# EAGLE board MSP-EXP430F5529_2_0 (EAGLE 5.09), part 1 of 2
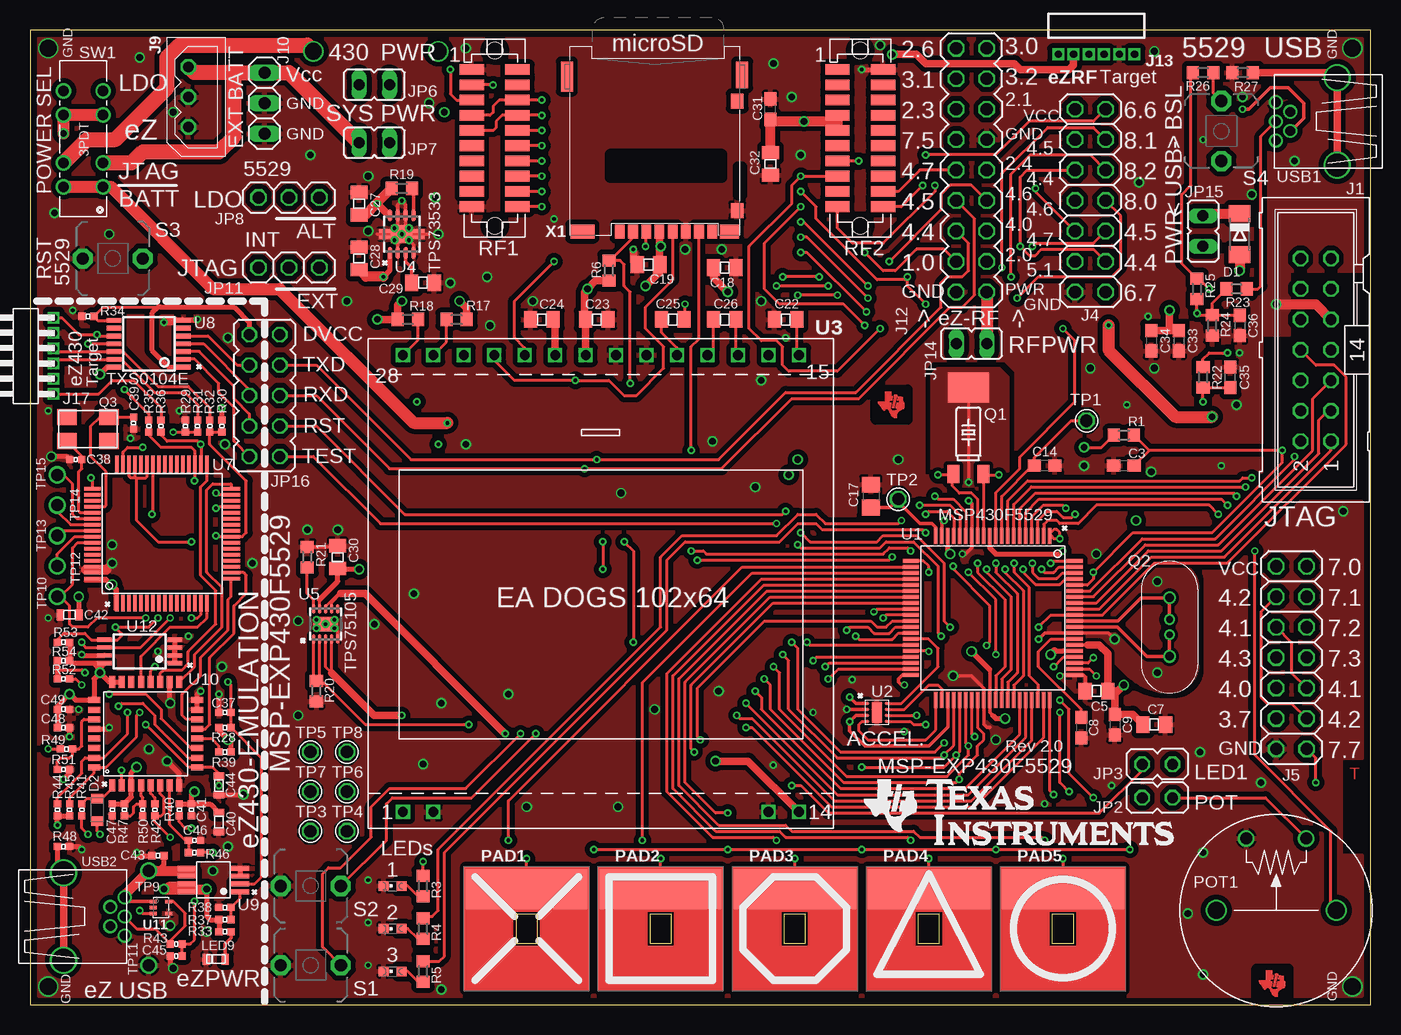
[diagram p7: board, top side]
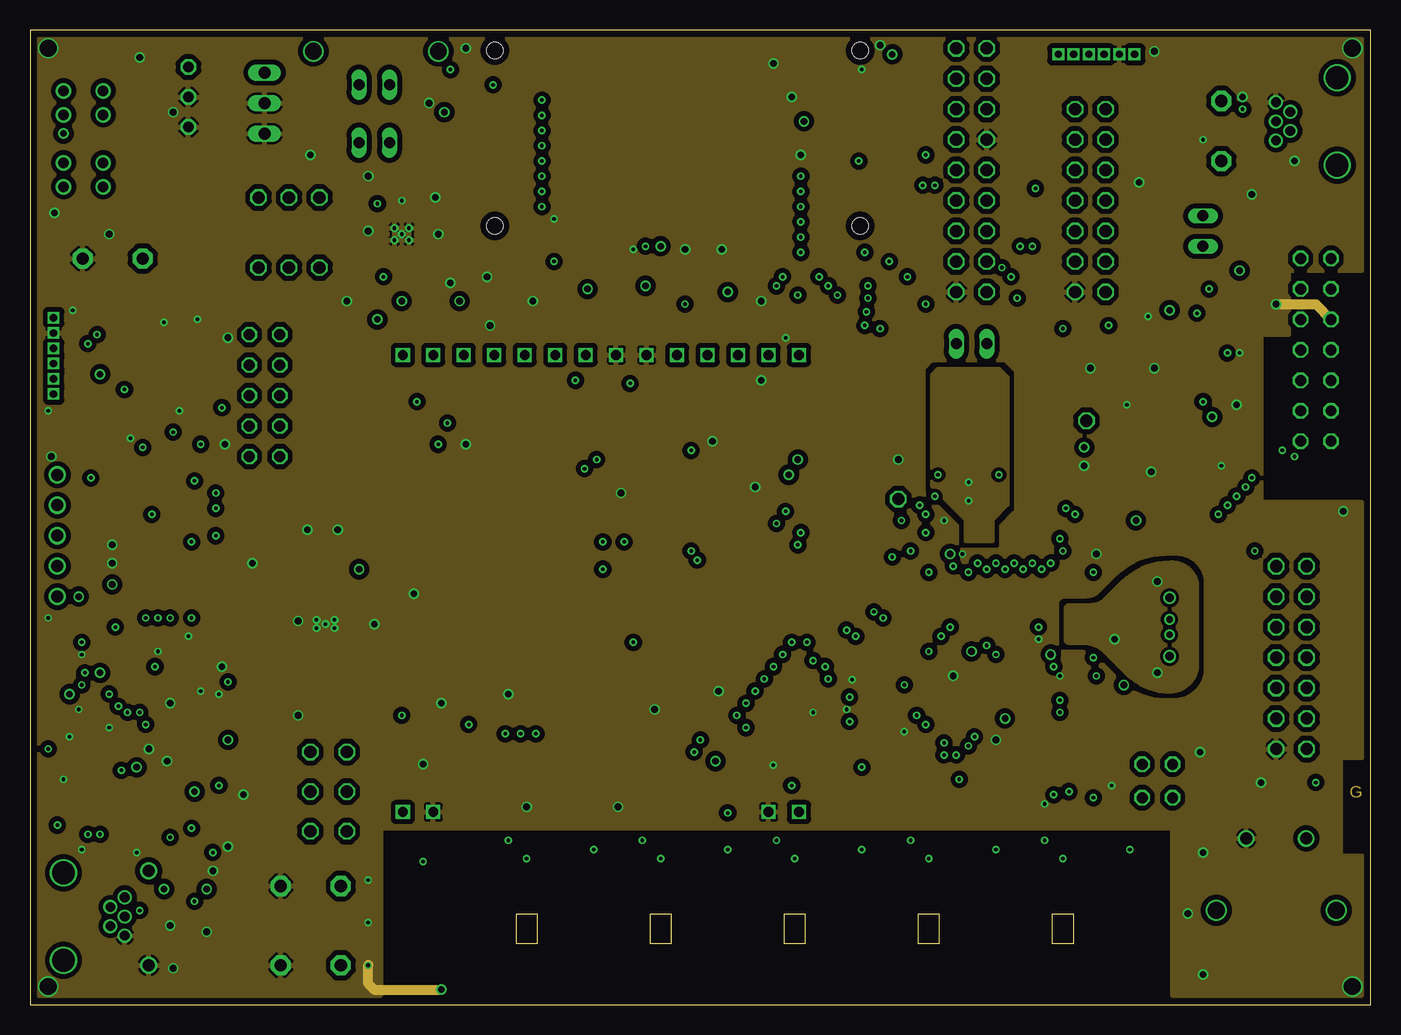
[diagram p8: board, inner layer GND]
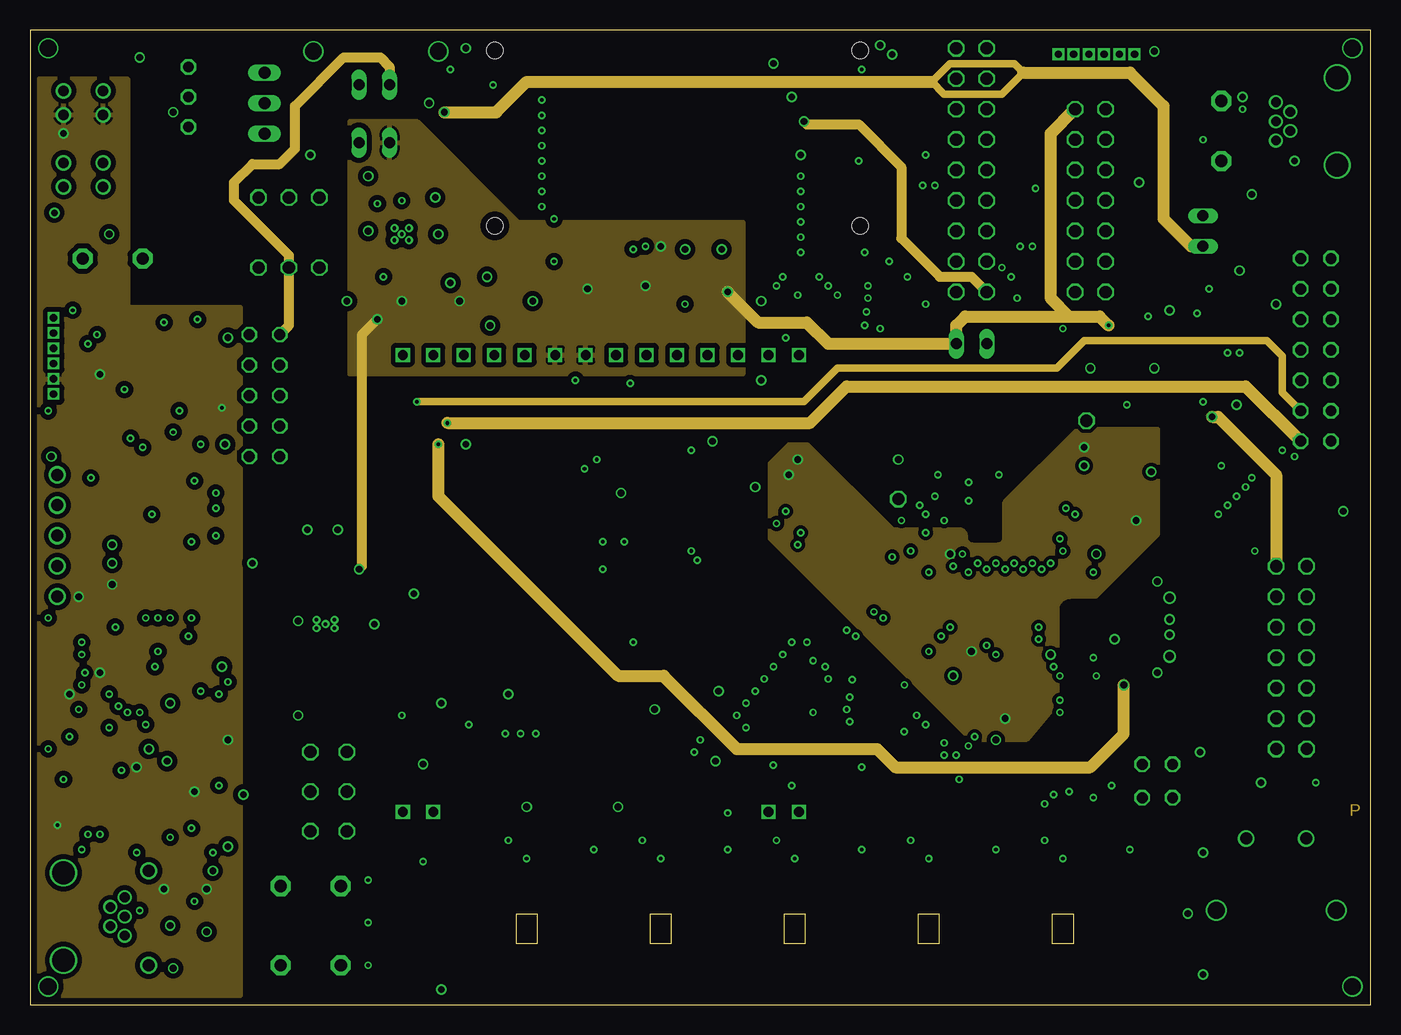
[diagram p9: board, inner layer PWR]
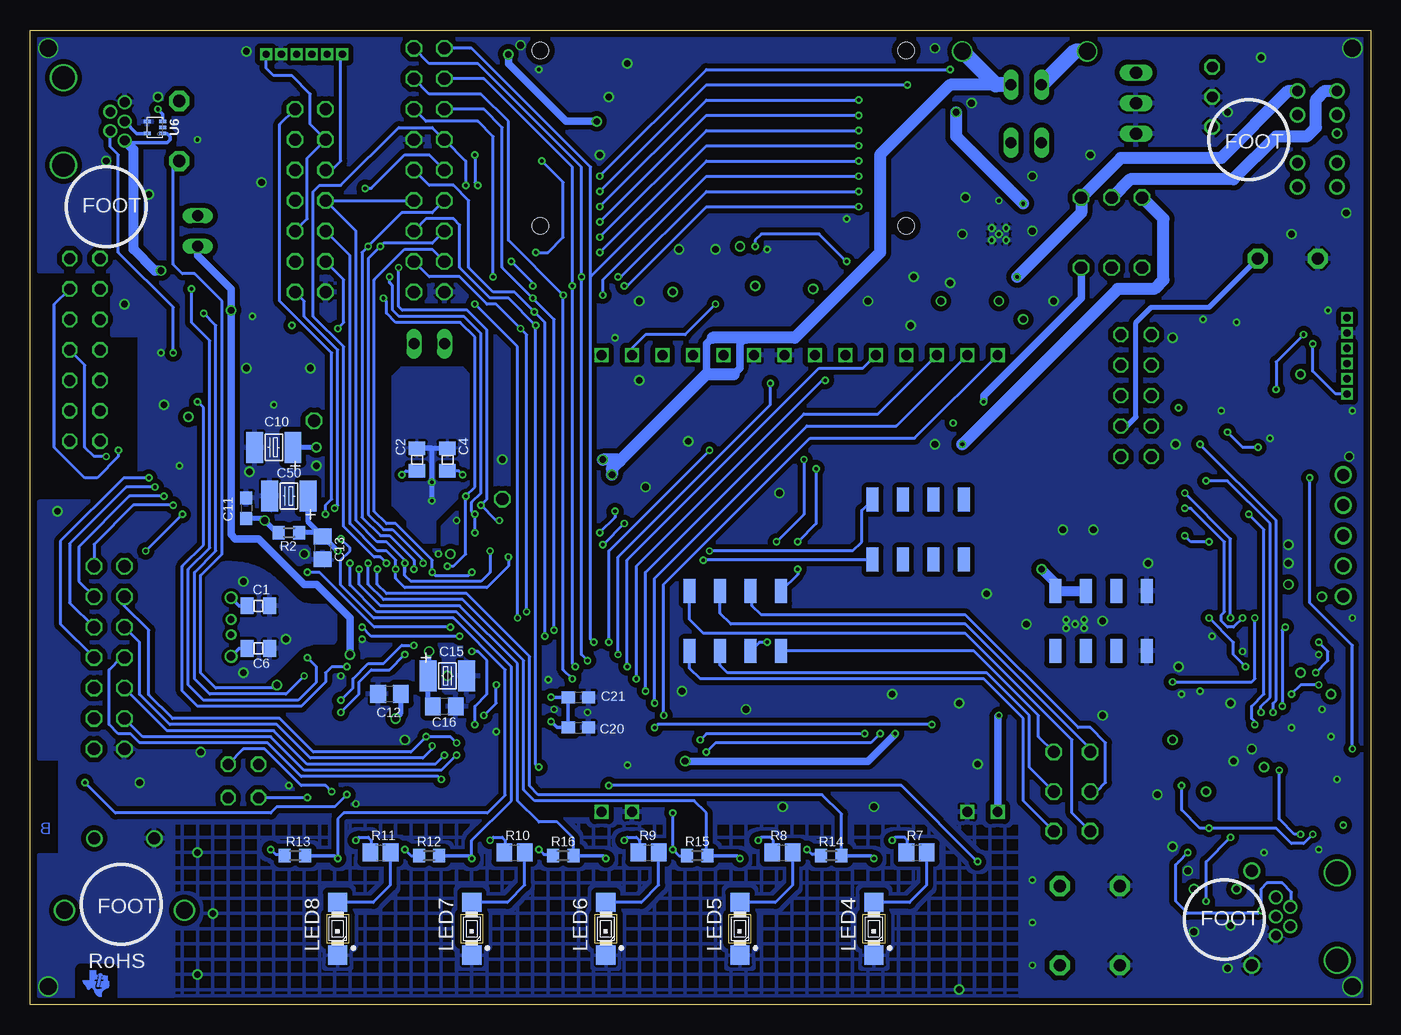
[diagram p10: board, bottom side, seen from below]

Size 111.76 x 81.28 mm. Coordinates in mm from the lower left corner, seen from the top.
Outline: 0,0 111.76,0 111.76,81.28 0,81.28 0,0
Copper layers (1+2*15+16): Top 0.0178mm / dielectric 0.3048mm / GND 0.0356mm / dielectric 0.6858mm / PWR 0.0356mm / dielectric 0.3048mm / Bottom 0.0178mm
Design rules "5529 Design Rules": minimum track width 6mil, minimum drill 12mil, track to track 6mil, track to pad 6mil, pad to pad 6mil, via to via 6mil, smd to smd 6mil, copper to edge 20mil, drill to drill 8mil, minimum pad ring 7mil, minimum via ring 6mil, stop-mask expansion 0mil, vias tented up to drill 25mil, thermal gap 8mil
Net classes: 0 Default: width 0.254 mm, drill 0.305 mm, clearance 0.152 mm; 1 Ground: width 0.305 mm, drill 0.305 mm, clearance 0.152 mm to class 0, clearance 0.152 mm; 2 Power: width 0.406 mm, drill 0.305 mm, clearance 0.152 mm to class 0, clearance 0.152 mm to class 1, clearance 0.152 mm

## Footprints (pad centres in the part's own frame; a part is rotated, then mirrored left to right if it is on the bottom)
CSMD0805 = smd 1.092 x 1.397: 1 -0.94,0; 2 0.94,0
C0603 = smd 1.1 x 1: 1 -0.85,0; 2 0.85,0
1210ELKO = smd 1.397 x 2.591: + 1.6,0; - -1.6,0
C0805 = smd 1.3 x 1.5: 1 -0.95,0; 2 0.95,0
0402 = smd 0.6 x 0.6: 1 -0.501,0; 2 0.501,0
0603 = smd 0.6 x 0.9: 1 -0.787,0; 2 0.787,0
8PIN_SM_MA_HEADER = smd 1 x 2: 1 -3.81,-2.5; 2 -3.81,2.5; 3 -1.27,-2.5; 4 -1.27,2.5; 5 1.27,-2.5; 6 1.27,2.5; 7 3.81,-2.5; 8 3.81,2.5
MINIMELF = smd 1.4 x 1.8: A 1.7,0; C -1.7,0
SOD110-R = smd 0.8 x 1: A 0.95,0; C -0.95,0
ML14 = drill 0.914 octagon: 1 -7.62,-1.27; 2 -7.62,1.27; 3 -5.08,-1.27; 4 -5.08,1.27; 5 -2.54,-1.27; 6 -2.54,1.27; 7 0,-1.27; 8 0,1.27; 9 2.54,-1.27; 10 2.54,1.27; 11 5.08,-1.27; 12 5.08,1.27; 13 7.62,-1.27; 14 7.62,1.27
2X07 = drill 1.016 octagon: 1 -7.62,-1.27; 2 -7.62,1.27; 3 -5.08,-1.27; 4 -5.08,1.27; 5 -2.54,-1.27; 6 -2.54,1.27; 7 0,-1.27; 8 0,1.27; 9 2.54,-1.27; 10 2.54,1.27; 11 5.08,-1.27; 12 5.08,1.27; 13 7.62,-1.27; 14 7.62,1.27
MOLEX-3P-HEADER = drill 0.9 pad 1.3 octagon: 1 2.5,0; 2 0,0; 3 -2.5,0
1X03 = drill 1.016 long: 1 -2.54,0; 2 0,0; 3 2.54,0
_MSP430_RF_MA09-2 = drill 1.016 octagon: 1 -10.16,1.27; 2 -10.16,-1.27; 3 -7.62,1.27; 4 -7.62,-1.27; 5 -5.08,1.27; 6 -5.08,-1.27; 7 -2.54,1.27; 8 -2.54,-1.27; 9 0,1.27; 10 0,-1.27; 11 2.54,1.27; 12 2.54,-1.27; 13 5.08,1.27; 14 5.08,-1.27; 15 7.62,1.27; 16 7.62,-1.27; 17 10.16,1.27; 18 10.16,-1.27
SL127L6 = drill 0.6 pad 1 square: 1 -3.175,0; 2 -1.905,0; 3 -0.635,0; 4 0.635,0; 5 1.905,0; 6 3.175,0
SL127L6_MPE = drill 0.6 pad 0.889 square: 1 -3.17,0.07; 2 -1.91,0.07; 3 -0.63,0.07; 4 0.63,0.07; 5 1.91,0.07; 6 3.18,0.07
JP1S = drill 0.914 octagon: 1 -1.27,0; 2 1.27,0
JP1 = drill 0.914 long: 1 0,-1.27; 2 0,1.27
1X03S = drill 1.016 octagon: 1 -2.54,0; 2 0,0; 3 2.54,0
JP5Q = drill 0.914 octagon: 1 -5.08,-1.27; 2 -5.08,1.27; 3 -2.54,-1.27; 4 -2.54,1.27; 5 0,-1.27; 6 0,1.27; 7 2.54,-1.27; 8 2.54,1.27; 9 5.08,-1.27; 10 5.08,1.27
CHIPLED_0603 = smd 0.8 x 0.8: A 0,-0.75; C 0,0.75
MINI-TOPLED-SANTANA = smd 1.6 x 1.6: A 0,2.2; C 0,-2.2
DIODE0603 = smd 0.6 x 0.9: A -0.787,0; K 0.787,0
CC430_PAD_NS = smd 10.16 x 3.302: 1 0,3.302
EVL-HFAA05B54 = drill 1 round: 1 -2.5,-6; 3 2.5,-6 | drill 1.4 round: 2 -5,0; 4 5,0
F20XX_PIR_DEMO_&_EVAL_CMJ206T = smd 1 x 1.5: P1 -1.25,-5; P2 1.25,-5 | smd 3.4 x 2.5: P3 0,2.2
QUARZ_HC49_4P = drill 0.7 round: 1 2.44,0; 2 -2.44,0 | drill 0.55 round: 1.1 0.635,0; 2.1 -0.635,0
FT10A = smd 1.6 x 1.35: P$1 -1.75,-1; P$2 1.75,-1; P$3 1.75,1; P$4 -1.75,1
R0603 = smd 1 x 1.1: 1 -0.85,0; 2 0.85,0
R0805 = smd 1.3 x 1.5: 1 -0.85,0; 2 0.85,0
TFM-110-02-SM-D-A-K = smd 2.032 x 0.889: 1 -1.27,5.08; 2 2.54,5.08; 3 -1.27,3.81; 4 2.54,3.81; 5 -1.27,2.54; 6 2.54,2.54; 7 -1.27,1.27; 8 2.54,1.27; 9 -1.27,0; 10 2.54,0; 11 -1.27,-1.27; 12 2.54,-1.27; 13 -1.27,-2.54; 14 2.54,-2.54; 15 -1.27,-3.81; 16 2.54,-3.81; 17 -1.27,-5.08; 18 2.54,-5.08; 19 -1.27,-6.35; 20 2.54,-6.35 | hole 1.359: 0.635,6.668; 0.635,-7.938
PBTH = drill 1.016 pad 1.676 octagon: 1 -0.001,0.001; 2 5.001,0.001
3PDT = drill 0.889 pad 1.27 round: 1 0,0; 2 2,0; 3 6,0; 4 8,0; 5 0,-3.3; 6 2,-3.3; 7 6,-3.3; 8 8,-3.3
TP = drill 1.016 octagon: 1 0,0
TP10 = drill 1 pad 1.422 round: 1 0,0
PN80 = smd 1.35 x 0.3: 1 -6.825,4.75; 2 -6.825,4.25; 3 -6.825,3.75; 4 -6.825,3.25; 5 -6.825,2.75; 6 -6.825,2.25; 7 -6.825,1.75; 8 -6.825,1.25; 9 -6.825,0.75; 10 -6.825,0.25; 11 -6.825,-0.25; 12 -6.825,-0.75; 13 -6.825,-1.25; 14 -6.825,-1.75; 15 -6.825,-2.25; 16 -6.825,-2.75; 17 -6.825,-3.25; 18 -6.825,-3.75; 19 -6.825,-4.25; 20 -6.825,-4.75; 41 6.825,-4.75; 42 6.825,-4.25; 43 6.825,-3.75; 44 6.825,-3.25; 45 6.825,-2.75; 46 6.825,-2.25; 47 6.825,-1.75; 48 6.825,-1.25; 49 6.825,-0.75; 50 6.825,-0.25; 51 6.825,0.25; 52 6.825,0.75; 53 6.825,1.25; 54 6.825,1.75; 55 6.825,2.25; 56 6.825,2.75; 57 6.825,3.25; 58 6.825,3.75; 59 6.825,4.25; 60 6.825,4.75 | smd 0.3 x 1.35: 21 -4.75,-6.825; 22 -4.25,-6.825; 23 -3.75,-6.825; 24 -3.25,-6.825; 25 -2.75,-6.825; 26 -2.25,-6.825; 27 -1.75,-6.825; 28 -1.25,-6.825; 29 -0.75,-6.825; 30 -0.25,-6.825; 31 0.25,-6.825; 32 0.75,-6.825; 33 1.25,-6.825; 34 1.75,-6.825; 35 2.25,-6.825; 36 2.75,-6.825; 37 3.25,-6.825; 38 3.75,-6.825; 39 4.25,-6.825; 40 4.75,-6.825; 61 4.75,6.825; 62 4.25,6.825; 63 3.75,6.825; 64 3.25,6.825; 65 2.75,6.825; 66 2.25,6.825; 67 1.75,6.825; 68 1.25,6.825; 69 0.75,6.825; 70 0.25,6.825; 71 -0.25,6.825; 72 -0.75,6.825; 73 -1.25,6.825; 74 -1.75,6.825; 75 -2.25,6.825; 76 -2.75,6.825; 77 -3.25,6.825; 78 -3.75,6.825; 79 -4.25,6.825; 80 -4.75,6.825
CMA3000-D01 = smd 0.275 x 0.275: 1 -0.75,-0.8; 2 -0.25,-0.8; 3 0.25,-0.8; 4 0.75,-0.8; 5 0.75,0.8; 6 0.25,0.8; 7 -0.25,0.8; 8 -0.75,0.8 | smd 1.8 x 0.9: 9 0,0
EADOGS102-6 = drill 0.813 square: 1 2.89,1.35; 2 5.43,1.35; 13 33.37,1.35; 14 35.91,1.35; 15 35.91,39.45; 16 33.37,39.45; 17 30.83,39.45; 18 28.29,39.45; 19 25.75,39.45; 20 23.21,39.45; 21 20.67,39.45; 22 18.13,39.45; 23 15.59,39.45; 24 13.05,39.45; 25 10.51,39.45; 26 7.97,39.45; 27 5.43,39.45; 28 2.89,39.45
DRB_S-PVSON-N8 = smd 0.35 x 1.025: 1 -0.975,-1.562; 2 -0.325,-1.562; 3 0.325,-1.562; 4 0.975,-1.562; 5 0.975,1.562; 6 0.325,1.562; 7 -0.325,1.562; 8 -0.975,1.562 | drill 0.305 round: PP@1 0,0; PP@2 -0.6,-0.5; PP@3 0.6,-0.5; PP@4 0.6,0.5; PP@5 -0.6,0.5 | smd 1.75 x 1.5: TH 0,0 | smd 3.8 x 0.28: TH@1 0,0.275; TH@2 0,-0.275
DSK_S-PDSO-N10 = smd 0.28 x 0.8: 1 -1,-1.25; 2 -0.5,-1.25; 3 0,-1.25; 4 0.5,-1.25; 5 1,-1.25; 6 1,1.25; 7 0.5,1.25; 8 0,1.25; 9 -0.5,1.25; 10 -1,1.25 | drill 0.3 round: P$1 0,0; P$2 0.75,0.35; P$3 0.75,-0.35; P$4 -0.75,-0.35; P$5 -0.75,0.35 | smd 2 x 1.2: PP 0,0
TPD2E001-DRL = smd 0.3 x 0.6: 1 -0.5,-0.65; 2 0,-0.65; 3 0.5,-0.65; 4 0.5,0.65; 5 -0.5,0.65
PM/PAG64 = smd 1.4 x 0.3: 1 -5.88,3.67; 2 -5.88,3.17; 3 -5.88,2.67; 4 -5.88,2.17; 5 -5.88,1.67; 6 -5.88,1.17; 7 -5.88,0.67; 8 -5.88,0.17; 9 -5.88,-0.33; 10 -5.88,-0.83; 11 -5.88,-1.33; 12 -5.88,-1.83; 13 -5.88,-2.33; 14 -5.88,-2.83; 15 -5.88,-3.33; 16 -5.88,-3.83; 33 5.72,-3.83; 34 5.72,-3.33; 35 5.72,-2.83; 36 5.72,-2.33; 37 5.72,-1.83; 38 5.72,-1.33; 39 5.72,-0.83; 40 5.72,-0.33; 41 5.72,0.17; 42 5.72,0.67; 43 5.72,1.17; 44 5.72,1.67; 45 5.72,2.17; 46 5.72,2.67; 47 5.72,3.17; 48 5.72,3.67 | smd 0.3 x 1.4: 17 -3.83,-5.88; 18 -3.33,-5.88; 19 -2.83,-5.88; 20 -2.33,-5.88; 21 -1.83,-5.88; 22 -1.33,-5.88; 23 -0.83,-5.88; 24 -0.33,-5.88; 25 0.17,-5.88; 26 0.67,-5.88; 27 1.17,-5.88; 28 1.67,-5.88; 29 2.17,-5.88; 30 2.67,-5.88; 31 3.17,-5.88; 32 3.67,-5.88; 49 3.67,5.72; 50 3.17,5.72; 51 2.67,5.72; 52 2.17,5.72; 53 1.67,5.72; 54 1.17,5.72; 55 0.67,5.72; 56 0.17,5.72; 57 -0.33,5.72; 58 -0.83,5.72; 59 -1.33,5.72; 60 -1.83,5.72; 61 -2.33,5.72; 62 -2.83,5.72; 63 -3.33,5.72; 64 -3.83,5.72
PW_R-PDSO-G14 = smd 0.4 x 1.2: 1 -1.95,-2.9; 2 -1.3,-2.9; 3 -0.65,-2.9; 4 0,-2.9; 5 0.65,-2.9; 6 1.3,-2.9; 7 1.95,-2.9; 8 1.95,2.9; 9 1.3,2.9; 10 0.65,2.9; 11 0,2.9; 12 -0.65,2.9; 13 -1.3,2.9; 14 -1.95,2.9
MSOP8 = smd 0.4 x 1.5: 1 -0.978,-2.3; 2 -0.333,-2.3; 3 0.323,-2.3; 4 0.968,-2.3; 5 0.968,2.18; 6 0.323,2.18; 7 -0.333,2.18; 8 -0.978,2.18
QFP32 = smd 0.5 x 1: 1 -2.8,-4.3; 2 -2,-4.3; 3 -1.2,-4.3; 4 -0.4,-4.3; 5 0.4,-4.3; 6 1.2,-4.3; 7 2,-4.3; 8 2.8,-4.3; 17 2.8,4.3; 18 2,4.3; 19 1.2,4.3; 20 0.4,4.3; 21 -0.4,4.3; 22 -1.2,4.3; 23 -2,4.3; 24 -2.8,4.3 | smd 1 x 0.5: 9 4.3,-2.8; 10 4.3,-2; 11 4.3,-1.2; 12 4.3,-0.4; 13 4.3,0.4; 14 4.3,1.2; 15 4.3,2; 16 4.3,2.8; 25 -4.3,2.8; 26 -4.3,2; 27 -4.3,1.2; 28 -4.3,0.4; 29 -4.3,-0.4; 30 -4.3,-1.2; 31 -4.3,-2; 32 -4.3,-2.8
USBFET_TSSOP8 = smd 1.2 x 0.35: 1 -2.925,0.975; 2 -2.925,0.325; 3 -2.925,-0.325; 4 -2.925,-0.975; 5 2.925,-0.975; 6 2.925,-0.325; 7 2.925,0.325; 8 2.925,0.975
USB-MB-H = drill 0.8 round: D+ 5.1,0; D- 3.9,0.8; GND 5.1,-1.6; ID 3.9,-0.8; VBUS 5.1,1.6 | drill 1.9 round: GND@1 0,3.65; GND@2 0,-3.65
SD-502702-003 = smd 0.8 x 1.16: 1 -2.9,-17.82; 2 -1.8,-17.82; 3 -0.7,-17.82; 4 0.4,-17.82; 5 1.5,-17.82; 6 2.6,-17.82; 7 3.7,-17.82; 8 4.8,-17.82 | smd 1.05 x 1.25: A 6.885,-16.075; B 6.885,-6.95 | smd 1 x 2.5: P$9 -7.3,-4.9 | smd 1 x 2.2: P$10 7.3,-4.75 | smd 2 x 1.16: P$11 -6.01,-17.82 | smd 1.6 x 1.16: P$12 6.24,-17.82

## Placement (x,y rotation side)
C1  47pF  [CSMD0805]  92.71,33.27 0 bottom
C2  12pF  [CSMD0805]  79.5,45.47 90 bottom
C3  DNP  [C0603]  91.19,44.96 0 top
C4  12pF  [CSMD0805]  76.96,45.47 90 bottom
C5  10µF  [CSMD0805]  88.9,26.16 180 top
C6  47pF  [CSMD0805]  92.71,29.72 0 bottom
C7  100nF  [CSMD0805]  93.73,23.37 0 top
C8  220n  [C0603]  87.63,23.11 270 top
C9  220n  [C0603]  90.42,23.37 270 top
C10  10uF/6,3V  [1210ELKO]  91.44,46.48 0 bottom
C11  100n  [C0603]  93.73,41.4 270 bottom
C12  100n  [C0805]  81.79,25.91 180 bottom
C13  100n  [C0805]  87.38,38.1 270 bottom
C14  DNP  [C0603]  84.58,44.96 180 top
C15  10uF/6,3V  [1210ELKO]  76.96,27.43 180 bottom
C16  100n  [C0805]  77.22,24.89 180 bottom
C17  470n  [C0805]  70.1,42.42 270 top
C18  10µF  [CSMD0805]  57.91,61.47 180 top
C19  100nF  [CSMD0805]  51.56,61.72 0 top
C20  .1u  [C0603]  66.04,23.11 0 bottom
C21  .1u  [C0603]  66.04,25.65 0 bottom
C22  1µF  [CSMD0805]  62.99,57.15 180 top
C23  1µF  [CSMD0805]  47.24,57.15 180 top
C24  1µF  [CSMD0805]  42.67,57.15 0 top
C25  1µF  [CSMD0805]  53.59,57.15 180 top
C26  1µF  [CSMD0805]  57.91,57.15 180 top
C27  1µF  [CSMD0805]  27.43,66.8 270 top
C28  4.7uF  [CSMD0805]  27.43,62.23 270 top
C29  10nF  [CSMD0805]  32.77,60.2 180 top
C30  1µF  [CSMD0805]  25.65,37.34 270 top
C31  .1u  [C0603]  61.72,74.68 90 top
C32  4.7u  [CSMD0805]  61.72,70.1 270 top
C33  0.1u  [C0603]  95.76,55.37 270 top
C34  4u7  [C0603]  93.47,55.37 270 top
C35  10p  [C0603]  100.08,52.32 90 top
C36  10p  [C0603]  100.84,56.64 270 top
C37  10n  [0402]  16.26,24.38 180 top
C38  33p  [0402]  3.81,45.47 180 top
C39  33p  [0402]  8.64,48.51 270 top
C40  1u/6.3V  [0603]  15.75,15.24 90 top
C41  100n  [0402]  13.46,16.26 270 top
C42  1u/6.3V  [0603]  3.3,32.51 180 top
C43  100n  [0402]  10.67,12.45 0 top
C44  1u/6.3V  [0603]  15.75,18.29 270 top
C45  22p  [0402]  12.19,4.06 0 top
C46  22p  [0402]  13.72,13.72 180 top
C47  100n  [0402]  6.86,16.26 90 top
C48  100n  [0402]  2.79,23.11 180 top
C49  100n  [0402]  2.79,24.64 0 top
C50  10uF/6,3V  [1210ELKO]  90.17,42.42 0 bottom
CON1  8PIN_SM_MA_HEADER  [8PIN_SM_MA_HEADER]  52.96,32 0 bottom
CON2  8PIN_SM_MA_HEADER  [8PIN_SM_MA_HEADER]  22.48,32 0 bottom
CON3  8PIN_SM_MA_HEADER  [8PIN_SM_MA_HEADER]  37.72,39.62 0 bottom
D1  SCHOTTKY  [MINIMELF]  100.84,64.26 270 top
D2  1N4148  [SOD110-R]  5.59,16.26 90 top
J1  [ML14]  107.19,54.61 90 top
J4  [2X07]  88.39,67.06 270 top
J5  [2X07]  105.16,28.96 270 top
J9  MOLEX3PIN  [MOLEX-3P-HEADER]  13.21,75.69 90 top
J10  PWR  [1X03]  19.56,75.18 90 top
J12  eZ-RF1  [_MSP430_RF_MA09-2]  78.49,69.6 90 top
J13  eZRF  [SL127L6]  88.9,79.25 0 top
J17  SL127L6TH  [SL127L6_MPE]  2.03,54.1 90 top
JP2  POT_JMP  [JP1S]  93.98,17.27 180 top
JP3  LED_JMP  [JP1S]  93.98,20.07 180 top
JP6  430_PWR  [JP1]  28.7,76.71 270 top
JP7  SYS_PWR  [JP1]  28.7,71.88 270 top
JP8  LDO_PWR_SEL  [1X03S]  21.59,67.31 0 top
JP11  JTAG_PWR_SEN  [1X03S]  21.59,61.47 180 top
JP14  RF_PWR  [JP1]  78.49,55.12 270 top
JP15  USB_PWR  [JP1]  97.79,64.52 0 top
JP16  eZ430-FET_JMP  [JP5Q]  19.56,50.8 90 top
LED1  [CHIPLED_0603]  30.23,9.91 90 top
LED2  [CHIPLED_0603]  30.23,6.35 90 top
LED3  [CHIPLED_0603]  30.23,2.79 90 top
LED4  [MINI-TOPLED-SANTANA]  41.4,6.35 0 bottom
LED5  [MINI-TOPLED-SANTANA]  52.58,6.35 0 bottom
LED6  [MINI-TOPLED-SANTANA]  63.75,6.35 0 bottom
LED7  [MINI-TOPLED-SANTANA]  74.93,6.35 0 bottom
LED8  [MINI-TOPLED-SANTANA]  86.11,6.35 0 bottom
LED9  green  [DIODE0603]  15.49,3.81 180 top
PAD1  PROJECT7264_CC430_PAD  [CC430_PAD_NS]  41.4,6.35 0 top
PAD2  PROJECT7264_CC430_PAD  [CC430_PAD_NS]  52.58,6.35 0 top
PAD3  PROJECT7264_CC430_PAD  [CC430_PAD_NS]  63.75,6.35 0 top
PAD4  PROJECT7264_CC430_PAD  [CC430_PAD_NS]  74.93,6.35 0 top
PAD5  PROJECT7264_CC430_PAD  [CC430_PAD_NS]  86.11,6.35 0 top
POT1  EVL-HFKA05B54  [EVL-HFAA05B54]  103.89,7.87 180 top
Q1  32.768kHz  [F20XX_PIR_DEMO_&_EVAL_CMJ206T]  78.23,49.28 0 top
Q2  QUARZ_HC49_4P-1  [QUARZ_HC49_4P]  95,31.5 270 top
Q3  12MHz  [FT10A]  4.83,48.01 0 top
R1  47k  [R0603]  91.19,47.5 180 top
R2  0R  [R0603]  90.17,39.37 180 bottom
R3  470R  [R0603]  32.77,9.91 270 top
R4  470R  [R0603]  32.77,6.35 270 top
R5  470R  [R0603]  32.77,2.79 270 top
R6  47k  [R0603]  48.26,61.21 90 top
R7  680  [R0805]  37.85,12.7 0 bottom
R8  680  [R0805]  49.02,12.7 0 bottom
R9  680  [R0805]  60.2,12.7 0 bottom
R10  680  [R0805]  71.37,12.7 0 bottom
R11  680  [R0805]  82.55,12.7 0 bottom
R12  100K  [R0603]  78.49,12.45 0 bottom
R13  100k  [R0603]  89.66,12.45 0 bottom
R14  100k  [R0603]  44.96,12.45 0 bottom
R15  100K  [R0603]  56.13,12.45 0 bottom
R16  100k  [R0603]  67.31,12.45 180 bottom
R17  47k  [R0603]  35.56,57.15 180 top
R18  47k  [R0603]  31.5,57.15 0 top
R19  0  [R0603]  30.99,68.07 180 top
R20  100k  [R0603]  23.88,26.16 90 top
R21  36k 1%  [R0603]  23.11,37.34 270 top
R22  27R  [R0603]  97.79,52.32 90 top
R23  27R  [R0603]  100.58,59.69 0 top
R24  1M  [R0603]  98.55,56.64 90 top
R25  1k4  [R0603]  97.28,59.69 270 top
R26  100R  [R0603]  97.79,77.72 0 top
R27  33k  [R0603]  101.09,77.72 0 top
R28  47k  [0402]  16.26,23.11 180 top
R29  47k  [0402]  12.95,48.26 90 top
R30  47k  [0402]  16,48.26 90 top
R31  100R  [0402]  13.97,48.26 90 top
R32  100R  [0402]  14.99,48.26 90 top
R33  270  [0402]  16.26,6.1 180 top
R34  DNP  [0402]  4.83,57.4 0 top
R35  100R  [0402]  9.91,48.26 90 top
R36  100R  [0402]  10.92,48.26 90 top
R37  6k8  [0402]  16.26,7.11 180 top
R38  3k3  [0402]  16.26,8.13 0 top
R39  10k  [0402]  16.26,21.08 0 top
R40  15k  [0402]  12.45,16.26 90 top
R41  33k  [0402]  4.32,16.26 270 top
R42  1k5  [0402]  10.41,16.26 90 top
R43  33R  [0402]  12.19,5.08 0 top
R44  47k  [0402]  2.29,16.26 270 top
R45  47k  [0402]  3.3,16.26 270 top
R46  33R  [0402]  13.72,12.7 180 top
R47  100k/1%  [0402]  7.87,16.26 90 top
R48  33k  [0402]  2.79,13.21 180 top
R49  3k3  [0402]  3.05,21.34 180 top
R50  100k/1%  [0402]  9.4,16.26 90 top
R51  3k3  [0402]  2.79,19.63 0 top
R52  100R  [0402]  2.79,27.18 0 top
R53  1k5  [0402]  2.79,30.23 180 top
R54  1k5  [0402]  2.79,28.7 180 top
RF1  [TFM-110-02-SM-D-A-K]  38.1,72.9 0 top
RF2  [TFM-110-02-SM-D-A-K]  68.58,72.9 0 top
S1  [PBTH]  25.91,3.3 180 top
S2  [PBTH]  25.91,9.91 180 top
S3  F5529_RST  [PBTH]  9.4,62.23 180 top
S4  USB_BSL  [PBTH]  99.31,70.36 90 top
SW1  [3PDT]  6.1,76.2 270 top
TP1  [TP]  88.07,48.7 180 top
TP2  [TP]  72.39,42.16 0 top
TP3  [TP]  23.37,14.48 0 top
TP4  [TP]  26.42,14.48 0 top
TP5  [TP]  23.37,21.08 0 top
TP6  [TP]  26.42,17.78 0 top
TP7  [TP]  23.37,17.78 0 top
TP8  [TP]  26.42,21.08 0 top
TP9  TP05TP10  [TP10]  9.91,11.18 90 top
TP10  TP05TP10  [TP10]  2.29,34.04 90 top
TP11  TP05TP10  [TP10]  9.91,3.3 90 top
TP12  TP05TP10  [TP10]  2.29,36.58 90 top
TP13  TP05TP10  [TP10]  2.29,39.12 90 top
TP14  TP05TP10  [TP10]  2.29,41.66 90 top
TP15  TP05TP10  [TP10]  2.29,44.2 90 top
U1  MSP430F5529IPNR  [PN80]  80.26,32.26 270 top
U2  CMA3000-D01  [CMA3000-D01]  70.61,24.38 270 top
U3  EA DOGS102-6 (LCD Display)  [EADOGS102-6]  28.19,14.73 0 top
U4  TPS73533  [DRB_S-PVSON-N8]  30.99,64.26 0 top
U5  TPS75105DSKR  [DSK_S-PDSO-N10]  24.64,31.75 0 top
U6  TPD2E001DRLR  [TPD2E001-DRL]  101.35,73.15 90 bottom
U7  MSP430F1612IPMR  [PM/PAG64]  10.92,39.37 90 top
U8  TXS0104EPWR  [PW_R-PDSO-G14]  9.91,55.12 90 top
U9  TPS77301DGK  [MSOP8]  15.24,10.41 90 top
U10  TUSB3410VF  [QFP32]  9.65,22.61 0 top
U11  TPD2E001DRLR  [TPD2E001-DRL]  10.92,8.13 270 top
U12  CAT24C128YI  [USBFET_TSSOP8]  9.14,29.46 180 top
U$1  [MSP430_LAB_TILOGO_SMALL]  71.88,50.29 0 top
U$2  [LOGO2008_TPLACE]  79.52,15.66 0 top
U$3  [MSP430_LAB_TILOGO_SMALL]  103.63,2.03 0 top
U$4  [MSP430_LAB_TILOGO_SMALL]  106.17,2.03 0 bottom
USB1  F5529 Mini-USB  [USB-MB-H]  108.97,73.66 180 top
USB2  eZ430-FET Mini-USB  [USB-MB-H]  2.79,7.37 0 top
X1  SD-502702-003-1  [SD-502702-003]  52.07,82.3 0 top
